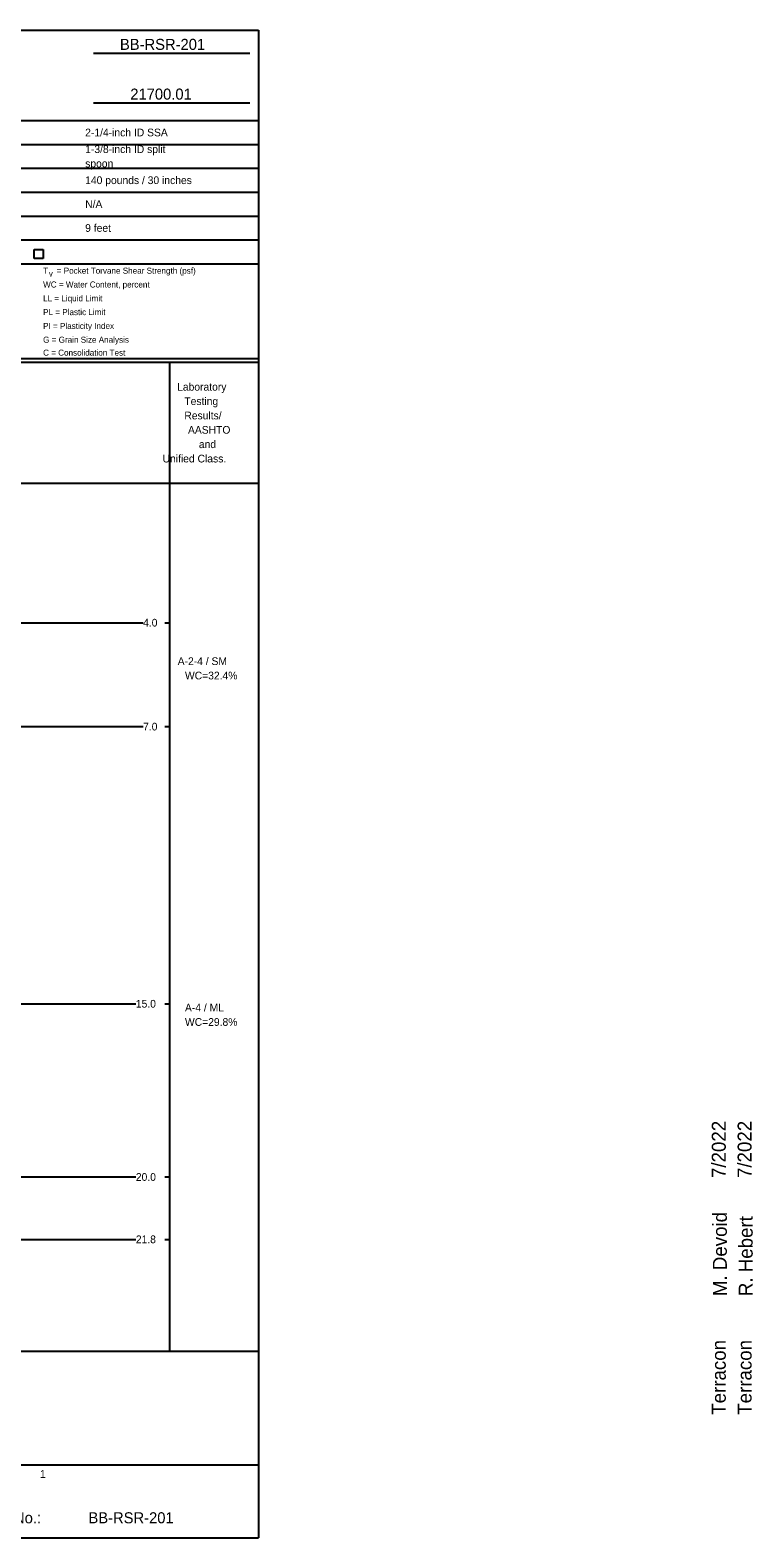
# Model space of a CAD drawing. Extents: x 9422 to 9552, y 6780 to 6860.
# Drawn here: x 9523.06 to 9543.93, y 6816.55 to 6860.07 of the extents above; entities that cross this region are included whole.
import ezdxf

# ---------------------------------------------------------------- set-up
doc = ezdxf.new("R2010")
doc.units = 0
doc.layers.add('7', color=7, linetype='Continuous')
doc.layers.add('H_V CONTROLS', color=7, linetype='Continuous')

msp = doc.modelspace()

# ---------------------------------------------------------------- linework, layer by layer
at = {"layer": '7'}
for p, q in [((9523.178, 6853.74), (9523.437, 6853.74)), ((9523.178, 6853.482), (9523.178, 6853.74)), ((9523.437, 6853.74), (9523.437, 6853.482)), ((9523.437, 6853.482), (9523.178, 6853.482)), ((9515.171, 6842.968), (9526.324, 6842.968)), ((9526.953, 6842.968), (9527.089, 6842.968)), ((9515.171, 6839.968), (9526.324, 6839.968)), ((9526.953, 6839.968), (9527.089, 6839.968)), ((9515.171, 6831.968), (9526.114, 6831.968)), ((9526.953, 6831.968), (9527.089, 6831.968)), ((9515.171, 6826.968), (9526.114, 6826.968)), ((9526.953, 6826.968), (9527.089, 6826.968))]:
    msp.add_line(p, q, dxfattribs=at)
for points in [[(9498.158, 6860.072), (9529.654, 6860.072)], [(9529.654, 6860.072), (9529.654, 6816.552)], [(9524.894, 6859.406), (9529.411, 6859.406)], [(9524.894, 6857.97), (9529.411, 6857.97)], [(9498.158, 6857.463), (9529.654, 6857.463)], [(9498.158, 6856.774), (9529.654, 6856.774)], [(9498.158, 6856.085), (9529.654, 6856.085)], [(9498.158, 6855.396), (9529.654, 6855.396)], [(9498.158, 6854.707), (9529.654, 6854.707)], [(9498.158, 6854.018), (9529.654, 6854.018)], [(9498.158, 6853.328), (9529.654, 6853.328)], [(9498.158, 6850.59), (9529.654, 6850.59)], [(9498.158, 6850.486), (9529.654, 6850.486)], [(9527.089, 6850.486), (9527.089, 6821.941)], [(9498.158, 6846.996), (9529.654, 6846.996)], [(9515.171, 6825.168), (9526.114, 6825.168)], [(9526.953, 6825.168), (9527.089, 6825.168)], [(9498.158, 6821.941), (9529.654, 6821.941)], [(9498.158, 6818.66), (9529.654, 6818.66)], [(9498.158, 6816.552), (9529.654, 6816.552)]]:
    msp.add_lwpolyline(points, dxfattribs=at)

# ---------------------------------------------------------------- texts
for s, height, p in [('BB-RSR-201', 0.3183, (9525.655, 6859.503)), ('21700.01', 0.3183, (9525.954, 6858.067)), ('2-1/4-inch ID SSA', 0.2228, (9524.651, 6857.007)), ('1-3/8-inch ID split', 0.2228, (9524.651, 6856.525)), ('spoon', 0.2228, (9524.651, 6856.111)), ('140 pounds / 30 inches', 0.2228, (9524.651, 6855.629)), ('N/A', 0.2228, (9524.651, 6854.94)), ('9 feet', 0.2228, (9524.651, 6854.251)), ('T', 0.175, (9523.436, 6853.042)), (' = Pocket Torvane Shear Strength (psf)', 0.17506, (9523.765, 6853.042)), ('WC = Water Content, percent', 0.17506, (9523.436, 6852.643)), ('v', 0.175, (9523.601, 6852.96)), ('LL = Liquid Limit', 0.17506, (9523.436, 6852.244)), ('PL = Plastic Limit', 0.17506, (9523.436, 6851.846)), ('PI = Plasticity Index', 0.17506, (9523.436, 6851.447)), ('G = Grain Size Analysis', 0.17506, (9523.436, 6851.049)), ('C = Consolidation Test', 0.17506, (9523.436, 6850.676)), ('Laboratory', 0.2228, (9527.306, 6849.665)), ('Testing ', 0.2228, (9527.515, 6849.251)), ('Results/', 0.2228, (9527.515, 6848.837)), ('AASHTO ', 0.2228, (9527.62, 6848.423)), ('and ', 0.2228, (9527.935, 6848.008)), ('Unified Class.', 0.2228, (9526.886, 6847.594)), ('4.0', 0.2228, (9526.324, 6842.857)), ('A-2-4 / SM', 0.2228, (9527.323, 6841.746)), ('WC=32.4%%%', 0.2228, (9527.533, 6841.331)), ('7.0', 0.2228, (9526.324, 6839.857)), ('15.0', 0.2228, (9526.114, 6831.857)), ('A-4 / ML', 0.2228, (9527.533, 6831.746)), ('WC=29.8%%%', 0.2228, (9527.533, 6831.331)), ('20.0', 0.2228, (9526.114, 6826.857)), ('21.8', 0.2228, (9526.114, 6825.057)), ('1', 0.223, (9523.345, 6818.283)), ('Boring No.:', 0.31829, (9521.248, 6816.972)), ('BB-RSR-201', 0.3183, (9524.746, 6816.972))]:
    msp.add_text(s, height=height, dxfattribs=at).set_placement(p)
at = {"layer": 'H_V CONTROLS'}
for s, p in [('7/2022', (9543.152, 6826.938)), ('7/2022', (9543.898, 6826.938)), ('M. Devoid', (9543.183, 6823.529)), ('R. Hebert', (9543.929, 6823.529)), ('Terracon', (9543.152, 6820.104)), ('Terracon', (9543.898, 6820.104))]:
    msp.add_text(s, height=0.4036, rotation=90, dxfattribs=at).set_placement(p)

doc.saveas('drawing.dxf')
